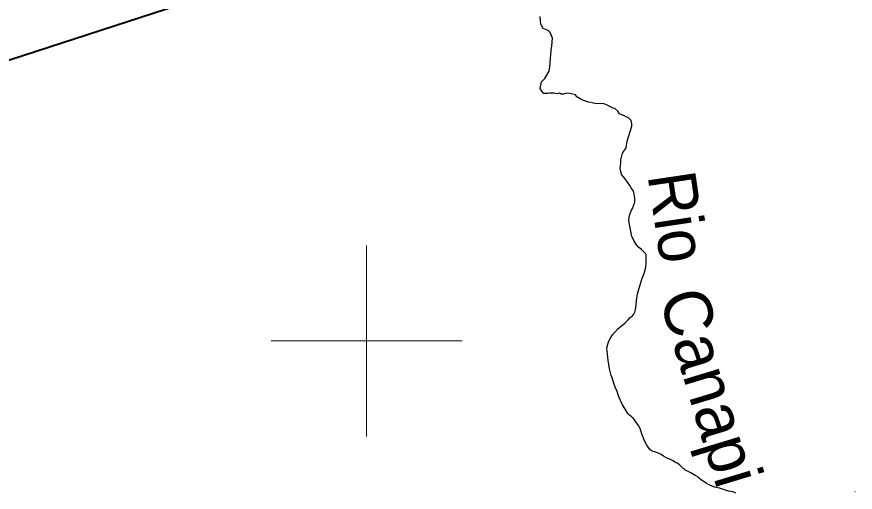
# Model space of a CAD drawing. Extents: x 553962 to 842807, y 8883888 to 9032388.
# Drawn here: x 646335 to 655119, y 8973416 to 8978393 of the extents above; entities that cross this region are included whole.
import ezdxf
from ezdxf.enums import TextEntityAlignment as Align

# ---------------------------------------------------------------- set-up
doc = ezdxf.new("R2010")
doc.units = 0
doc.header["$LTSCALE"] = 200
for name, color, linetype, lineweight in [('12', 7, 'Continuous', 25), ('2', 7, 'Continuous', 13), ('24', 7, 'Continuous', 25)]:
    doc.layers.add(name, color=color, linetype=linetype, lineweight=lineweight)
doc.layers.add('49', color=7, linetype='Continuous')

msp = doc.modelspace()

# ---------------------------------------------------------------- linework, layer by layer
at = {"layer": '12', "lineweight": 40}
msp.add_line((636526.5, 8974783.6), (662912, 8983353), dxfattribs=at)
at = {"layer": '2'}
for p, q in [((650000, 8974000), (650000, 8976000)), ((649000, 8975000), (651000, 8975000))]:
    msp.add_line(p, q, dxfattribs=at)
at = {"layer": '24'}
msp.add_line((655116.6, 8973422.7), (655117, 8973424.3), dxfattribs=at)
for points in [[(652771.6, 8977307.6), (652743.6, 8977336.7), (652700, 8977355.6), (652648.8, 8977376.5), (652631.7, 8977406.9), (652599.1, 8977434.4), (652582.3, 8977435.4), (652567.8, 8977444.9), (652514, 8977471.5), (652479.8, 8977484.8), (652430.5, 8977481), (652391.1, 8977486.8), (652363.3, 8977492), (652326.1, 8977499.9), (652255.9, 8977522.7), (652202.8, 8977555), (652189.5, 8977577.8), (652130.7, 8977591.1), (652098.4, 8977593), (652062.3, 8977583.5), (652039.6, 8977583.5), (652020.6, 8977593), (651997.8, 8977587.3), (651961.8, 8977593), (651916.2, 8977594.9), (651899.2, 8977589.2), (651855.5, 8977591.1), (651834.4, 8977616.2), (651817.7, 8977643.9), (651832.7, 8977712.6), (651866.9, 8977748.7), (651911.5, 8977823.3), (651916.2, 8977847.4), (651920, 8977866.4), (651923.8, 8977910.1), (651933.3, 8978039.2), (651940.9, 8978090.4), (651948.5, 8978170.2), (651923.8, 8978229), (651901.1, 8978248), (651851.2, 8978272.3), (651826.5, 8978315.8), (651820.6, 8978351), (651819.5, 8978396.3)], [(652799.8, 8975280.4), (652809.8, 8975302.2), (652816.1, 8975328.3), (652822.4, 8975374.6), (652826.9, 8975422.5), (652839.8, 8975493.2), (652864.5, 8975587.5), (652888.2, 8975655.6), (652908, 8975704.5), (652925.9, 8975773.4), (652929.4, 8975820.5), (652930.5, 8975902.1), (652923, 8975914.4), (652902.1, 8975937.5), (652881.4, 8975957.1), (652852.2, 8975978.9), (652827.9, 8976005.5), (652801.9, 8976045.7), (652783.3, 8976090.1), (652777.5, 8976093.8), (652748.7, 8976257.8), (652752.2, 8976297.8), (652759.6, 8976332.9), (652774.2, 8976369.2), (652784.3, 8976387.2), (652805.5, 8976443.3), (652809.5, 8976460.7), (652811.3, 8976493), (652801.1, 8976555.8), (652798.8, 8976558), (652796.5, 8976566.6), (652771.4, 8976603.6), (652757.2, 8976628.1), (652709.4, 8976696.7), (652669.3, 8976741.1), (652663.9, 8976773), (652657.8, 8976807.6), (652663.9, 8976859.5), (652664.9, 8976895.8), (652682.2, 8976964.3), (652718.6, 8977021.2), (652730, 8977089.5), (652778.6, 8977249)], [(652778.6, 8977249), (652777.9, 8977274.4), (652771.6, 8977307.6)], [(653869.2, 8973406.6), (653838.8, 8973418.7), (653790.9, 8973428.7), (653697.5, 8973459.4), (653649.6, 8973468.4), (653604, 8973484.9), (653582.4, 8973495.6), (653556.1, 8973510.9), (653509.5, 8973541.4), (653482.9, 8973561.9), (653470.5, 8973577.6), (653442.6, 8973592.3), (653395.4, 8973620.1), (653335.2, 8973650.9), (653328.8, 8973657.6), (653317.1, 8973665.3), (653282.9, 8973700.4), (653261.2, 8973715), (653237, 8973727.3), (653213.3, 8973743.3), (653191.4, 8973755.3), (653143.5, 8973777.1), (653134.4, 8973779.3), (653111.9, 8973795.2), (653085.1, 8973811.8), (653065.5, 8973821.4), (653019.2, 8973837.3), (653002.9, 8973840.6), (652981, 8973851.6), (652965.9, 8973864.6), (652937, 8973909.3), (652911.1, 8973953), (652887.5, 8974017.3), (652874.5, 8974060.1), (652864.8, 8974083.7), (652850.2, 8974112.8), (652813.3, 8974163.9), (652794.5, 8974187.8), (652771, 8974210.2), (652753.5, 8974223.6), (652741.1, 8974236.2), (652681.1, 8974329.2), (652660, 8974375.6), (652651, 8974399.9), (652639.3, 8974423.5), (652623.5, 8974469.8), (652603.2, 8974516.9), (652579.3, 8974588.4), (652572.8, 8974612), (652562.8, 8974637.3), (652546.2, 8974706.2), (652532.2, 8974799.6), (652526.8, 8974824.9), (652519.2, 8974897.6), (652518.3, 8974918.3), (652521.3, 8974941), (652527.4, 8974967.1), (652535.4, 8974989), (652558, 8975036.1), (652577.2, 8975063.9), (652631.7, 8975125.9), (652648.1, 8975141.2), (652704.5, 8975187.2), (652741, 8975221.5), (652762.8, 8975244.2), (652783.3, 8975259.7), (652799.8, 8975280.4)]]:
    msp.add_lwpolyline(points, dxfattribs=at)

# ---------------------------------------------------------------- texts
at = {"layer": '49', "width": 0.95}
msp.add_text('Rio', height=500, rotation=278.527, dxfattribs=at).set_placement((653013, 8976261.9), align=Align.CENTER)
at = {"layer": '49'}
msp.add_text('Canapi', height=500, rotation=286.879, dxfattribs=at).set_placement((653368, 8974444.7), align=Align.CENTER)

doc.saveas('drawing.dxf')
